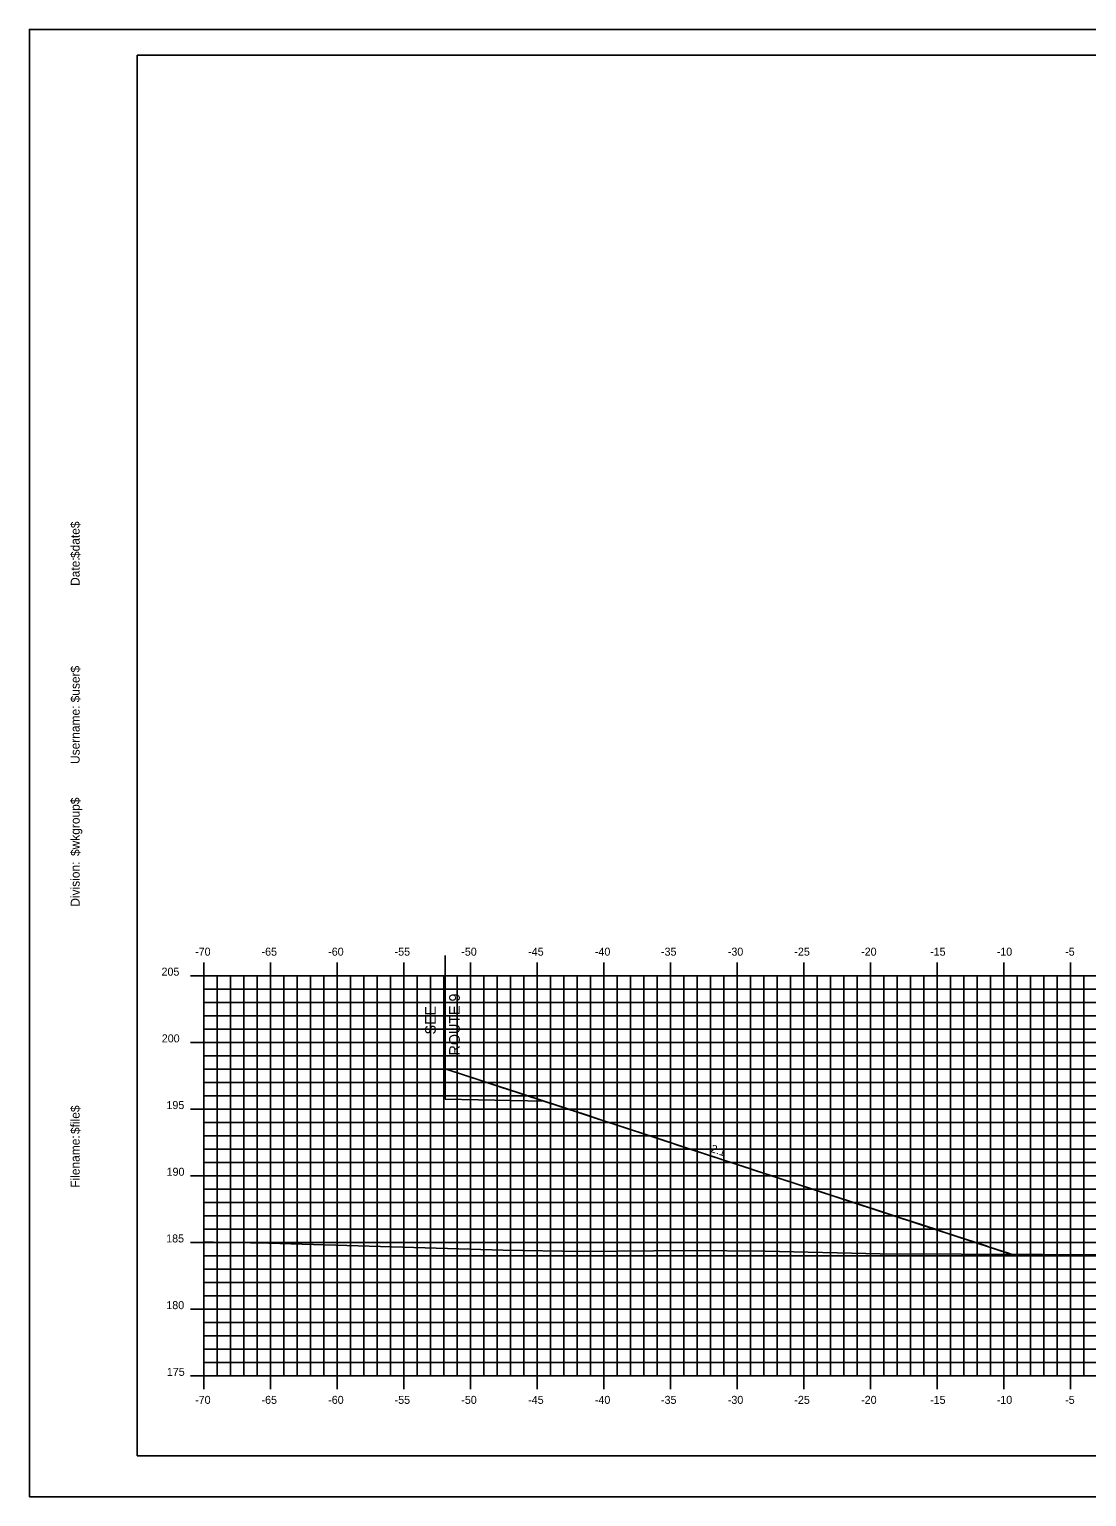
# Model space of a CAD drawing. Extents: x 1724848 to 1725020, y 459560 to 459670.
# Drawn here: x 1724848.4 to 1724927.7, y 459559.6 to 459669.6 of the extents above; entities that cross this region are included whole.
import ezdxf

# ---------------------------------------------------------------- set-up
doc = ezdxf.new("R2010")
doc.units = 0
for name, color, linetype in [('ANNOTATION', 7, 'Continuous'), ('BORDER', 7, 'Continuous'), ('D_Roadway_Centerline', 7, 'Continuous'), ('D_Roadway_Edge_Shoulder', 7, 'Continuous'), ('D_Roadway_SlopeLines', 7, 'Continuous'), ('D_Roadway_SubGrade', 7, 'Continuous'), ('H_V ANNOTATION', 7, 'Continuous'), ('MAJOR', 7, 'Continuous'), ('MINOR', 7, 'Continuous'), ('PLOT BOUNDARY', 7, 'Continuous'), ('S_Roadway_Centerline', 7, 'Continuous')]:
    doc.layers.add(name, color=color, linetype=linetype)

msp = doc.modelspace()

# ---------------------------------------------------------------- linework, layer by layer
at = {"layer": 'BORDER'}
msp.add_lwpolyline([(1724856.5, 459562.61), (1725016.5, 459562.61), (1725016.5, 459667.61), (1724856.5, 459667.61)], close=True, dxfattribs=at)
at = {"layer": 'D_Roadway_Centerline'}
msp.add_lwpolyline([(1724879.59, 459591.63), (1724882.48, 459590.68), (1724883.85, 459590.23), (1724884.88, 459589.9), (1724887.02, 459589.19), (1724887.38, 459589.08), (1724887.41, 459589.07), (1724890.46, 459588.07), (1724890.79, 459587.96), (1724892.11, 459587.53), (1724892.34, 459587.45), (1724895.63, 459586.38), (1724896.7, 459586.03), (1724897.1, 459585.89), (1724897.27, 459585.84), (1724900.33, 459584.84), (1724902.2, 459584.23), (1724902.43, 459584.15), (1724902.61, 459584.09), (1724904.84, 459583.36), (1724907.13, 459582.61), (1724907.7, 459582.42), (1724908.52, 459582.16), (1724909.77, 459581.75), (1724912.06, 459581), (1724913.87, 459580.4), (1724914.43, 459580.22), (1724916.58, 459579.52), (1724916.99, 459579.38), (1724920.16, 459578.35), (1724920.34, 459578.28), (1724921.91, 459577.77), (1724921.92, 459577.77), (1724922.1, 459577.71)], dxfattribs=at)
at = {"layer": 'D_Roadway_Edge_Shoulder'}
msp.add_line((1724879.59, 459591.63), (1724879.59, 459591.38), dxfattribs=at)
msp.add_line((1724879.59, 459591.63), (1724879.59, 459591.38), dxfattribs=at)
msp.add_line((1724879.59, 459591.63), (1724879.59, 459591.38), dxfattribs=at)
at = {"layer": 'D_Roadway_SlopeLines'}
msp.add_lwpolyline([(1724879.59, 459591.63), (1724922.1, 459577.71)], dxfattribs=at)
at = {"layer": 'D_Roadway_SubGrade'}
msp.add_line((1724879.59, 459600.13), (1724879.59, 459589.35), dxfattribs=at)
msp.add_lwpolyline([(1724879.59, 459591.38), (1724879.59, 459591.63), (1724887.02, 459589.19), (1724879.59, 459589.35)], dxfattribs=at)
msp.add_lwpolyline([(1724879.59, 459591.38), (1724879.59, 459591.63), (1724887.02, 459589.19), (1724879.59, 459589.35)], dxfattribs=at)
at = {"layer": 'MAJOR'}
for p, q in [((1724861.5, 459599.61), (1724861.5, 459598.61)), ((1724866.5, 459599.61), (1724866.5, 459598.61)), ((1724871.5, 459599.61), (1724871.5, 459598.61)), ((1724876.5, 459599.61), (1724876.5, 459598.61)), ((1724881.5, 459599.61), (1724881.5, 459598.61)), ((1724886.5, 459599.61), (1724886.5, 459598.61)), ((1724891.5, 459599.61), (1724891.5, 459598.61)), ((1724896.5, 459599.61), (1724896.5, 459598.61)), ((1724901.5, 459599.61), (1724901.5, 459598.61)), ((1724906.5, 459599.61), (1724906.5, 459598.61)), ((1724911.5, 459599.61), (1724911.5, 459598.61)), ((1724916.5, 459599.61), (1724916.5, 459598.61)), ((1724921.5, 459599.61), (1724921.5, 459598.61)), ((1724926.5, 459599.61), (1724926.5, 459598.61)), ((1724860.5, 459598.61), (1724861.5, 459598.61)), ((1724861.5, 459598.61), (1725001.5, 459598.61)), ((1724861.5, 459568.61), (1724861.5, 459598.61)), ((1724861.5, 459568.61), (1724861.5, 459598.61)), ((1724861.5, 459598.61), (1725001.5, 459598.61)), ((1724866.5, 459568.61), (1724866.5, 459598.61)), ((1724871.5, 459568.61), (1724871.5, 459598.61)), ((1724876.5, 459568.61), (1724876.5, 459598.61)), ((1724881.5, 459568.61), (1724881.5, 459598.61)), ((1724886.5, 459568.61), (1724886.5, 459598.61)), ((1724891.5, 459568.61), (1724891.5, 459598.61)), ((1724896.5, 459568.61), (1724896.5, 459598.61)), ((1724901.5, 459568.61), (1724901.5, 459598.61)), ((1724906.5, 459568.61), (1724906.5, 459598.61)), ((1724911.5, 459568.61), (1724911.5, 459598.61)), ((1724916.5, 459568.61), (1724916.5, 459598.61)), ((1724921.5, 459568.61), (1724921.5, 459598.61)), ((1724926.5, 459568.61), (1724926.5, 459598.61)), ((1724860.5, 459593.61), (1724861.5, 459593.61)), ((1724861.5, 459593.61), (1725001.5, 459593.61)), ((1724860.5, 459588.61), (1724861.5, 459588.61)), ((1724861.5, 459588.61), (1725001.5, 459588.61)), ((1724860.5, 459583.61), (1724861.5, 459583.61)), ((1724861.5, 459583.61), (1725001.5, 459583.61)), ((1724860.5, 459578.61), (1724861.5, 459578.61)), ((1724861.5, 459578.61), (1725001.5, 459578.61)), ((1724860.5, 459573.61), (1724861.5, 459573.61)), ((1724861.5, 459573.61), (1725001.5, 459573.61)), ((1724860.5, 459568.61), (1724861.5, 459568.61)), ((1724861.5, 459568.61), (1725001.5, 459568.61)), ((1724861.5, 459568.61), (1725001.5, 459568.61)), ((1724861.5, 459567.61), (1724861.5, 459568.61)), ((1724866.5, 459567.61), (1724866.5, 459568.61)), ((1724871.5, 459567.61), (1724871.5, 459568.61)), ((1724876.5, 459567.61), (1724876.5, 459568.61)), ((1724881.5, 459567.61), (1724881.5, 459568.61)), ((1724886.5, 459567.61), (1724886.5, 459568.61)), ((1724891.5, 459567.61), (1724891.5, 459568.61)), ((1724896.5, 459567.61), (1724896.5, 459568.61)), ((1724901.5, 459567.61), (1724901.5, 459568.61)), ((1724906.5, 459567.61), (1724906.5, 459568.61)), ((1724911.5, 459567.61), (1724911.5, 459568.61)), ((1724916.5, 459567.61), (1724916.5, 459568.61)), ((1724921.5, 459567.61), (1724921.5, 459568.61)), ((1724926.5, 459567.61), (1724926.5, 459568.61))]:
    msp.add_line(p, q, dxfattribs=at)
at = {"layer": 'MINOR'}
for p, q in [((1724861.5, 459597.61), (1725001.5, 459597.61)), ((1724861.5, 459597.61), (1724862.5, 459597.61)), ((1724862.5, 459568.61), (1724862.5, 459598.61)), ((1724863.5, 459568.61), (1724863.5, 459598.61)), ((1724864.5, 459568.61), (1724864.5, 459598.61)), ((1724865.5, 459568.61), (1724865.5, 459598.61)), ((1724867.5, 459568.61), (1724867.5, 459598.61)), ((1724868.5, 459568.61), (1724868.5, 459598.61)), ((1724869.5, 459568.61), (1724869.5, 459598.61)), ((1724870.5, 459568.61), (1724870.5, 459598.61)), ((1724872.5, 459568.61), (1724872.5, 459598.61)), ((1724873.5, 459568.61), (1724873.5, 459598.61)), ((1724874.5, 459568.61), (1724874.5, 459598.61)), ((1724875.5, 459568.61), (1724875.5, 459598.61)), ((1724877.5, 459568.61), (1724877.5, 459598.61)), ((1724878.5, 459568.61), (1724878.5, 459598.61)), ((1724879.5, 459568.61), (1724879.5, 459598.61)), ((1724880.5, 459568.61), (1724880.5, 459598.61)), ((1724882.5, 459568.61), (1724882.5, 459598.61)), ((1724883.5, 459568.61), (1724883.5, 459598.61)), ((1724884.5, 459568.61), (1724884.5, 459598.61)), ((1724885.5, 459568.61), (1724885.5, 459598.61)), ((1724887.5, 459568.61), (1724887.5, 459598.61)), ((1724888.5, 459568.61), (1724888.5, 459598.61)), ((1724889.5, 459568.61), (1724889.5, 459598.61)), ((1724890.5, 459568.61), (1724890.5, 459598.61)), ((1724892.5, 459568.61), (1724892.5, 459598.61)), ((1724893.5, 459568.61), (1724893.5, 459598.61)), ((1724894.5, 459568.61), (1724894.5, 459598.61)), ((1724895.5, 459568.61), (1724895.5, 459598.61)), ((1724897.5, 459568.61), (1724897.5, 459598.61)), ((1724898.5, 459568.61), (1724898.5, 459598.61)), ((1724899.5, 459568.61), (1724899.5, 459598.61)), ((1724900.5, 459568.61), (1724900.5, 459598.61)), ((1724902.5, 459568.61), (1724902.5, 459598.61)), ((1724903.5, 459568.61), (1724903.5, 459598.61)), ((1724904.5, 459568.61), (1724904.5, 459598.61)), ((1724905.5, 459568.61), (1724905.5, 459598.61)), ((1724907.5, 459568.61), (1724907.5, 459598.61)), ((1724908.5, 459568.61), (1724908.5, 459598.61)), ((1724909.5, 459568.61), (1724909.5, 459598.61)), ((1724910.5, 459568.61), (1724910.5, 459598.61)), ((1724912.5, 459568.61), (1724912.5, 459598.61)), ((1724913.5, 459568.61), (1724913.5, 459598.61)), ((1724914.5, 459568.61), (1724914.5, 459598.61)), ((1724915.5, 459568.61), (1724915.5, 459598.61)), ((1724917.5, 459568.61), (1724917.5, 459598.61)), ((1724918.5, 459568.61), (1724918.5, 459598.61)), ((1724919.5, 459568.61), (1724919.5, 459598.61)), ((1724920.5, 459568.61), (1724920.5, 459598.61)), ((1724922.5, 459568.61), (1724922.5, 459598.61)), ((1724923.5, 459568.61), (1724923.5, 459598.61)), ((1724924.5, 459568.61), (1724924.5, 459598.61)), ((1724925.5, 459568.61), (1724925.5, 459598.61)), ((1724927.5, 459568.61), (1724927.5, 459598.61)), ((1724861.5, 459596.61), (1725001.5, 459596.61)), ((1724861.5, 459596.61), (1724862.5, 459596.61)), ((1724861.5, 459595.61), (1725001.5, 459595.61)), ((1724861.5, 459595.61), (1724862.5, 459595.61)), ((1724861.5, 459594.61), (1725001.5, 459594.61)), ((1724861.5, 459594.61), (1724862.5, 459594.61)), ((1724861.5, 459592.61), (1725001.5, 459592.61)), ((1724861.5, 459592.61), (1724862.5, 459592.61)), ((1724861.5, 459591.61), (1725001.5, 459591.61)), ((1724861.5, 459591.61), (1724862.5, 459591.61)), ((1724861.5, 459590.61), (1725001.5, 459590.61)), ((1724861.5, 459590.61), (1724862.5, 459590.61)), ((1724861.5, 459589.61), (1725001.5, 459589.61)), ((1724861.5, 459589.61), (1724862.5, 459589.61)), ((1724861.5, 459587.61), (1725001.5, 459587.61)), ((1724861.5, 459587.61), (1724862.5, 459587.61)), ((1724861.5, 459586.61), (1725001.5, 459586.61)), ((1724861.5, 459586.61), (1724862.5, 459586.61)), ((1724861.5, 459585.61), (1725001.5, 459585.61)), ((1724861.5, 459585.61), (1724862.5, 459585.61)), ((1724861.5, 459584.61), (1725001.5, 459584.61)), ((1724861.5, 459584.61), (1724862.5, 459584.61)), ((1724861.5, 459582.61), (1725001.5, 459582.61)), ((1724861.5, 459582.61), (1724862.5, 459582.61)), ((1724861.5, 459581.61), (1725001.5, 459581.61)), ((1724861.5, 459581.61), (1724862.5, 459581.61)), ((1724861.5, 459580.61), (1725001.5, 459580.61)), ((1724861.5, 459580.61), (1724862.5, 459580.61)), ((1724861.5, 459579.61), (1725001.5, 459579.61)), ((1724861.5, 459579.61), (1724862.5, 459579.61)), ((1724861.5, 459577.61), (1725001.5, 459577.61)), ((1724861.5, 459577.61), (1724862.5, 459577.61)), ((1724861.5, 459576.61), (1725001.5, 459576.61)), ((1724861.5, 459576.61), (1724862.5, 459576.61)), ((1724861.5, 459575.61), (1725001.5, 459575.61)), ((1724861.5, 459575.61), (1724862.5, 459575.61)), ((1724861.5, 459574.61), (1725001.5, 459574.61)), ((1724861.5, 459574.61), (1724862.5, 459574.61)), ((1724861.5, 459572.61), (1725001.5, 459572.61)), ((1724861.5, 459572.61), (1724862.5, 459572.61)), ((1724861.5, 459571.61), (1725001.5, 459571.61)), ((1724861.5, 459571.61), (1724862.5, 459571.61)), ((1724861.5, 459570.61), (1725001.5, 459570.61)), ((1724861.5, 459570.61), (1724862.5, 459570.61)), ((1724861.5, 459569.61), (1725001.5, 459569.61)), ((1724861.5, 459569.61), (1724862.5, 459569.61))]:
    msp.add_line(p, q, dxfattribs=at)
at = {"layer": 'PLOT BOUNDARY'}
msp.add_lwpolyline([(1724848.41, 459559.55), (1725018.41, 459559.55), (1725018.41, 459669.55), (1724848.41, 459669.55)], close=True, dxfattribs=at)
at = {"layer": 'S_Roadway_Centerline'}
msp.add_lwpolyline([(1724861.5, 459578.62), (1724862.22, 459578.63), (1724866.37, 459578.56), (1724883.95, 459578.02), (1724889.86, 459577.92), (1724897.91, 459578), (1724903.58, 459577.95), (1724912.22, 459577.75), (1724924.38, 459577.7), (1724924.82, 459577.69), (1724945.04, 459577.73), (1724949.34, 459577.68), (1724959.96, 459577.17), (1724967.19, 459577.52), (1724975.1, 459577.53), (1724988.6, 459577.24), (1724994.92, 459577.09), (1725001.5, 459577.04)], dxfattribs=at)

# ---------------------------------------------------------------- texts
at = {"layer": 'ANNOTATION'}
for s, height, rotation, p in [('ROUTE 9', 0.8, 90, (1724880.69, 459592.63)), ('SEE', 0.8, 90, (1724878.89, 459594.2)), ('2:1', 0.6, 341.5651, (1724899.46, 459585.41))]:
    msp.add_text(s, height=height, rotation=rotation, dxfattribs=at).set_placement(p)
at = {"layer": 'BORDER'}
for s, p in [('$date$', (1724852.18, 459629.92)), ('Date:', (1724852.18, 459627.83)), ('$user$', (1724852.18, 459619.1)), ('Username:', (1724852.18, 459614.48)), ('$wkgroup$', (1724852.18, 459607.58)), ('Division:', (1724852.18, 459603.78)), ('$file$', (1724852.18, 459586.74)), ('Filename:', (1724852.18, 459582.71))]:
    msp.add_text(s, height=0.67, rotation=90, dxfattribs=at).set_placement(p)
at = {"layer": 'H_V ANNOTATION'}
for s, p in [('-70', (1724860.84, 459600.11)), ('-65', (1724865.82, 459600.11)), ('-60', (1724870.82, 459600.11)), ('-55', (1724875.8, 459600.11)), ('-50', (1724880.8, 459600.11)), ('-45', (1724885.82, 459600.11)), ('-40', (1724890.82, 459600.11)), ('-35', (1724895.78, 459600.11)), ('-30', (1724900.79, 459600.11)), ('-25', (1724905.78, 459600.11)), ('-20', (1724910.79, 459600.11)), ('-15', (1724915.96, 459600.11)), ('-10', (1724920.96, 459600.11)), ('-5', (1724926.09, 459600.11)), ('205', (1724858.32, 459598.61)), ('200', (1724858.34, 459593.61)), ('195', (1724858.69, 459588.61)), ('190', (1724858.7, 459583.61)), ('185', (1724858.67, 459578.61)), ('180', (1724858.68, 459573.61)), ('175', (1724858.72, 459568.61)), ('-70', (1724860.84, 459566.51)), ('-65', (1724865.82, 459566.51)), ('-60', (1724870.82, 459566.51)), ('-55', (1724875.8, 459566.51)), ('-50', (1724880.8, 459566.51)), ('-45', (1724885.82, 459566.51)), ('-40', (1724890.82, 459566.51)), ('-35', (1724895.78, 459566.51)), ('-30', (1724900.79, 459566.51)), ('-25', (1724905.78, 459566.51)), ('-20', (1724910.79, 459566.51)), ('-15', (1724915.96, 459566.51)), ('-10', (1724920.96, 459566.51)), ('-5', (1724926.09, 459566.51))]:
    msp.add_text(s, height=0.6, dxfattribs=at).set_placement(p)
at = {"layer": 'MAJOR'}
msp.add_text('-', height=0.006, dxfattribs=at).set_placement((1724861.49, 459568.61))

doc.saveas('drawing.dxf')
